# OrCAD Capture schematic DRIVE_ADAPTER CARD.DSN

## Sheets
1 03. Or'ing Circuit: size A4; title: XMC DRIVER ADAPTER CARD; rev: 3.00; note: 630-INT0222-01
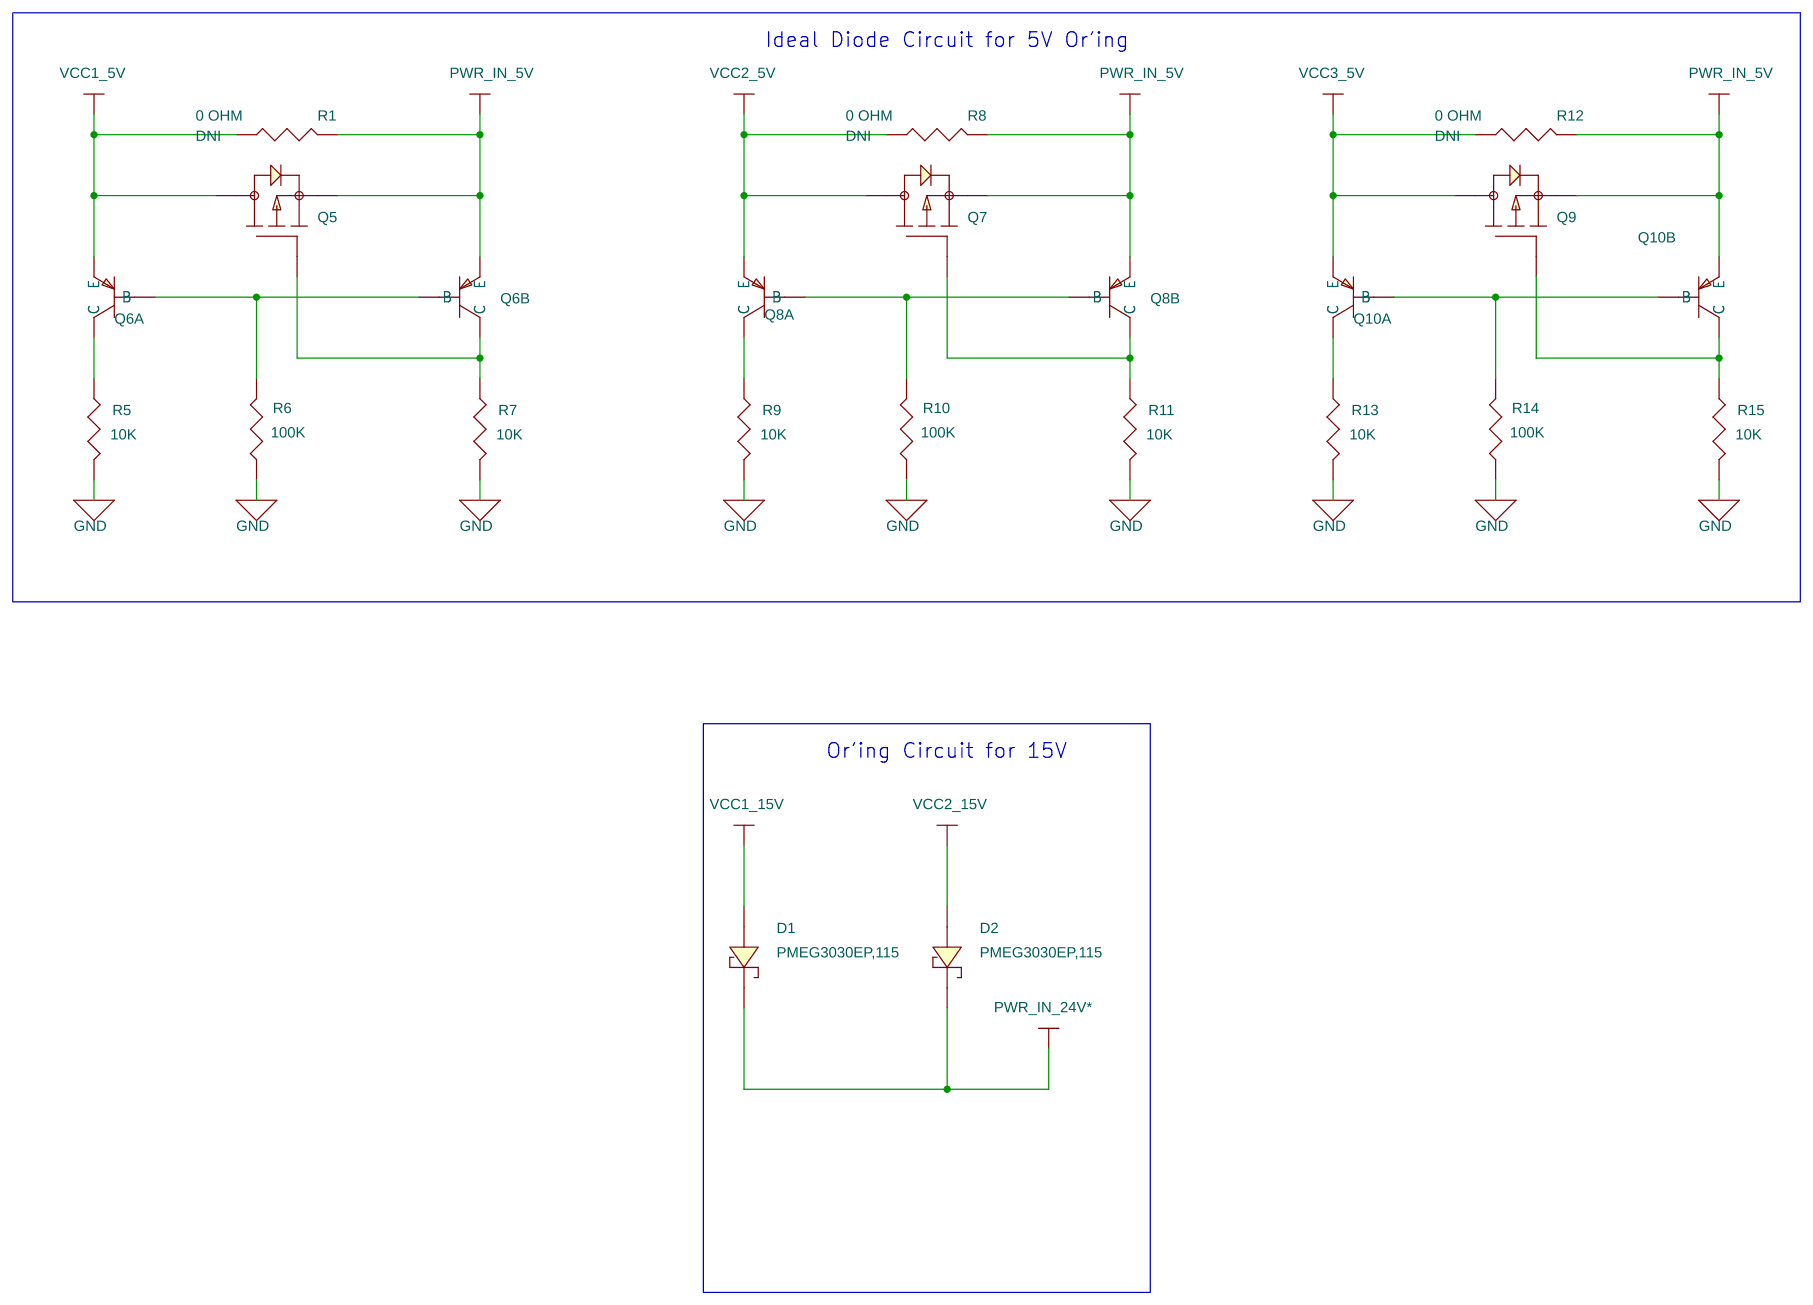
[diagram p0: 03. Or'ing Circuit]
2 01. Title Page
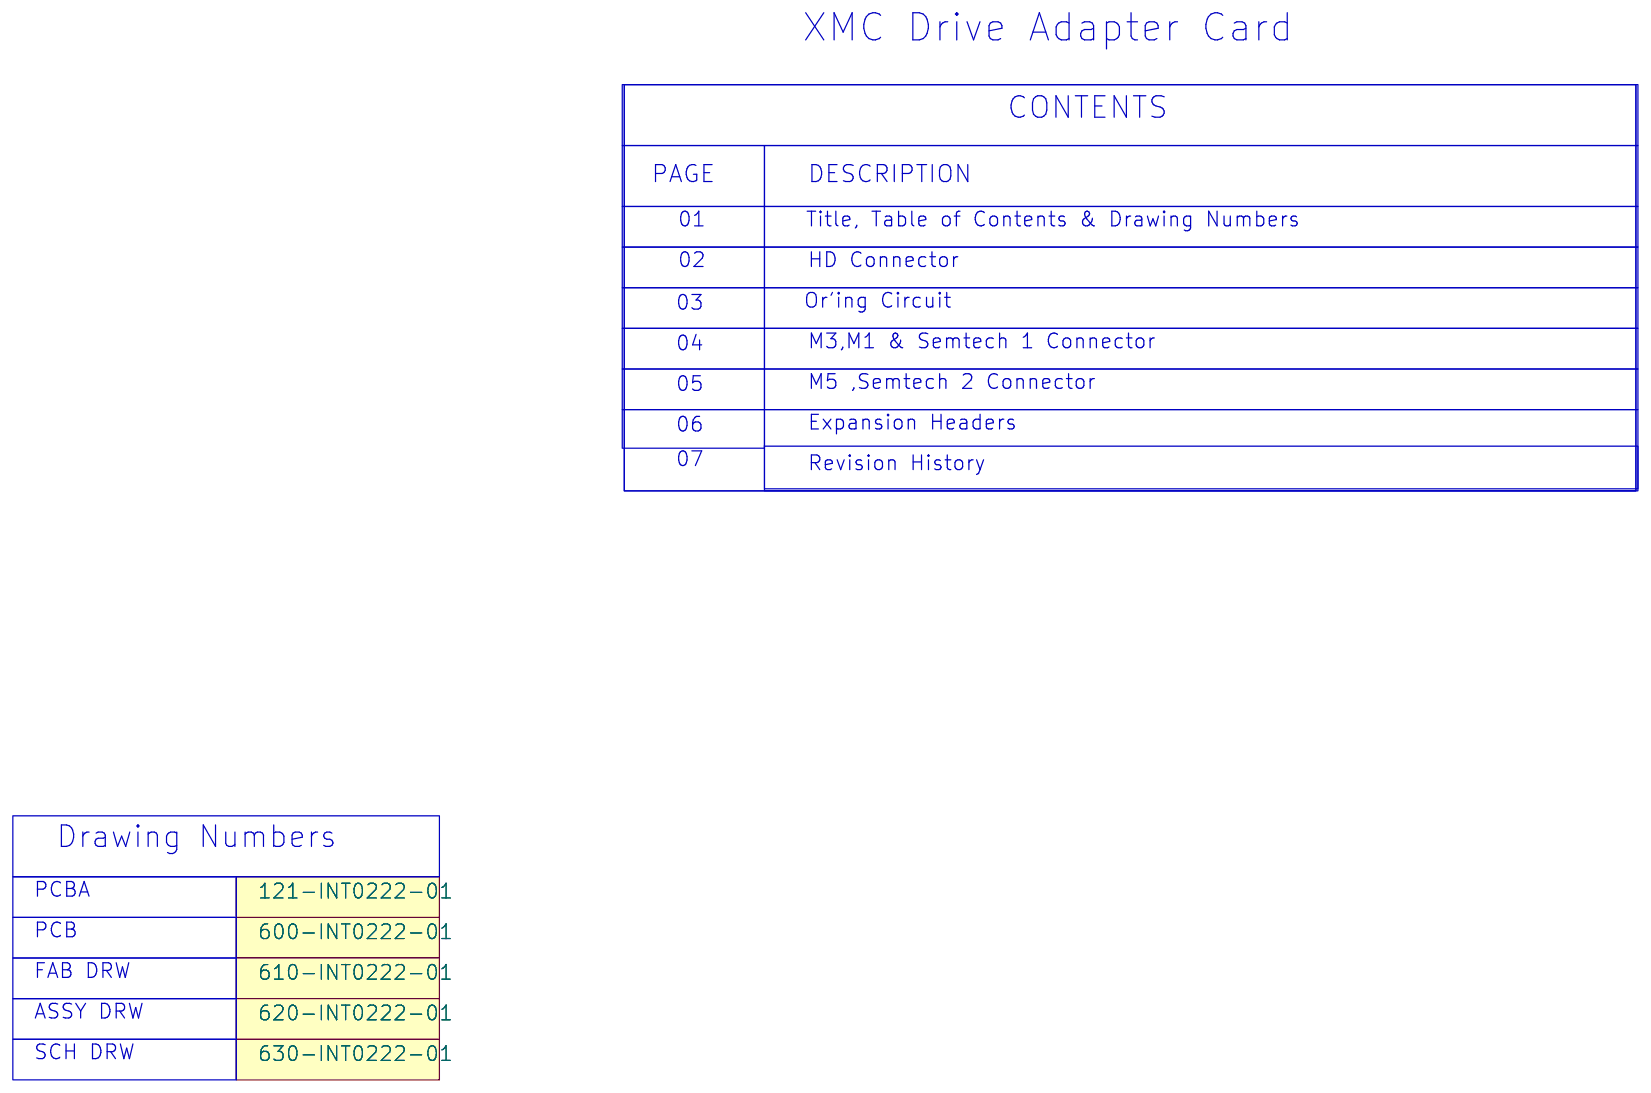
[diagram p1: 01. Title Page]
3 02. HD Connector: size A4
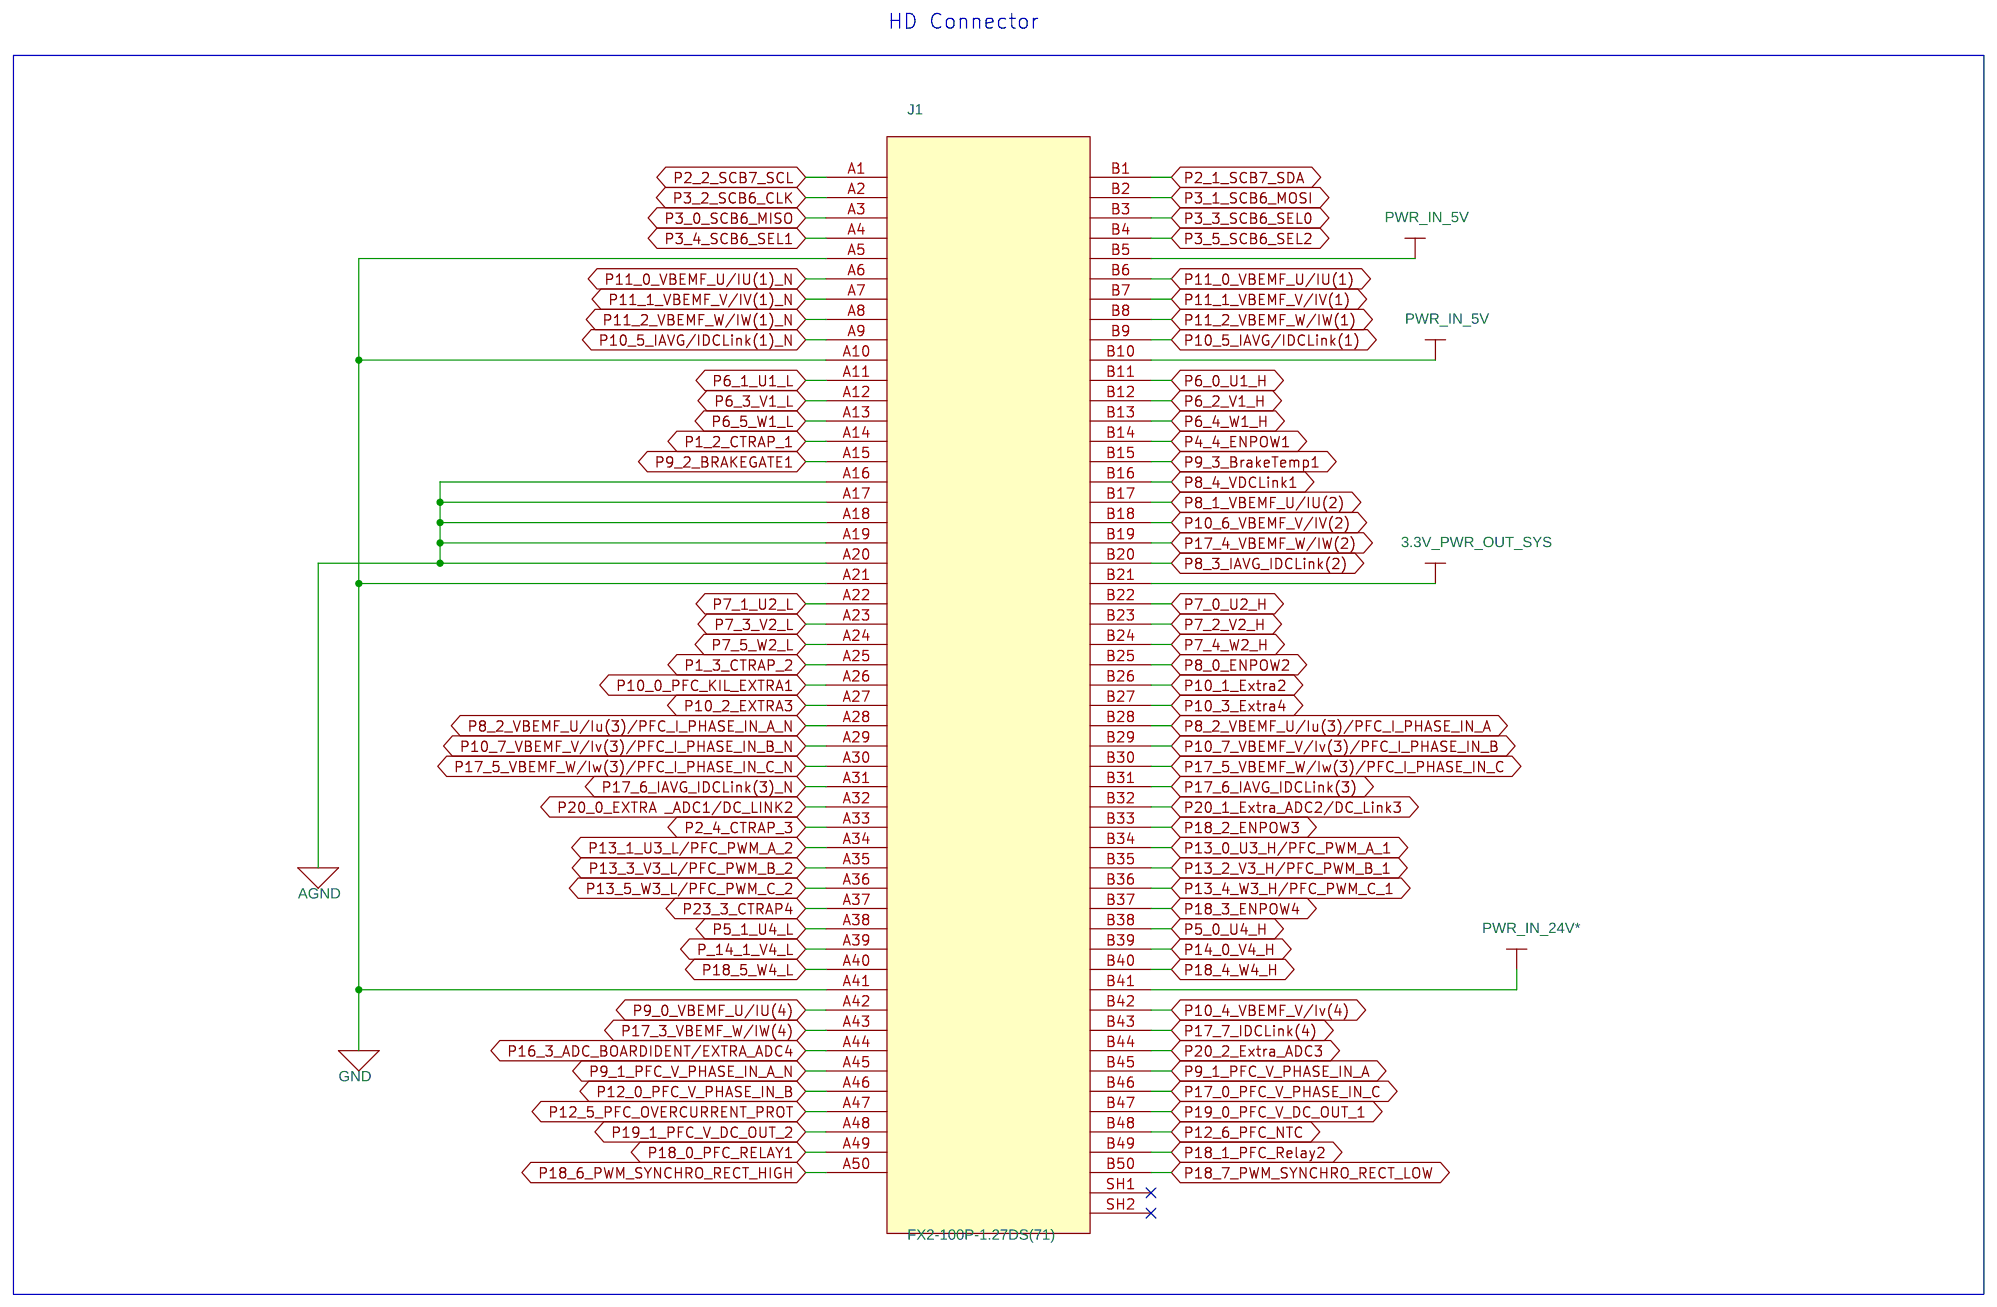
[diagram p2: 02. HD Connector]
4 04.M3,M1 & Semtech 1 Connector: size A4
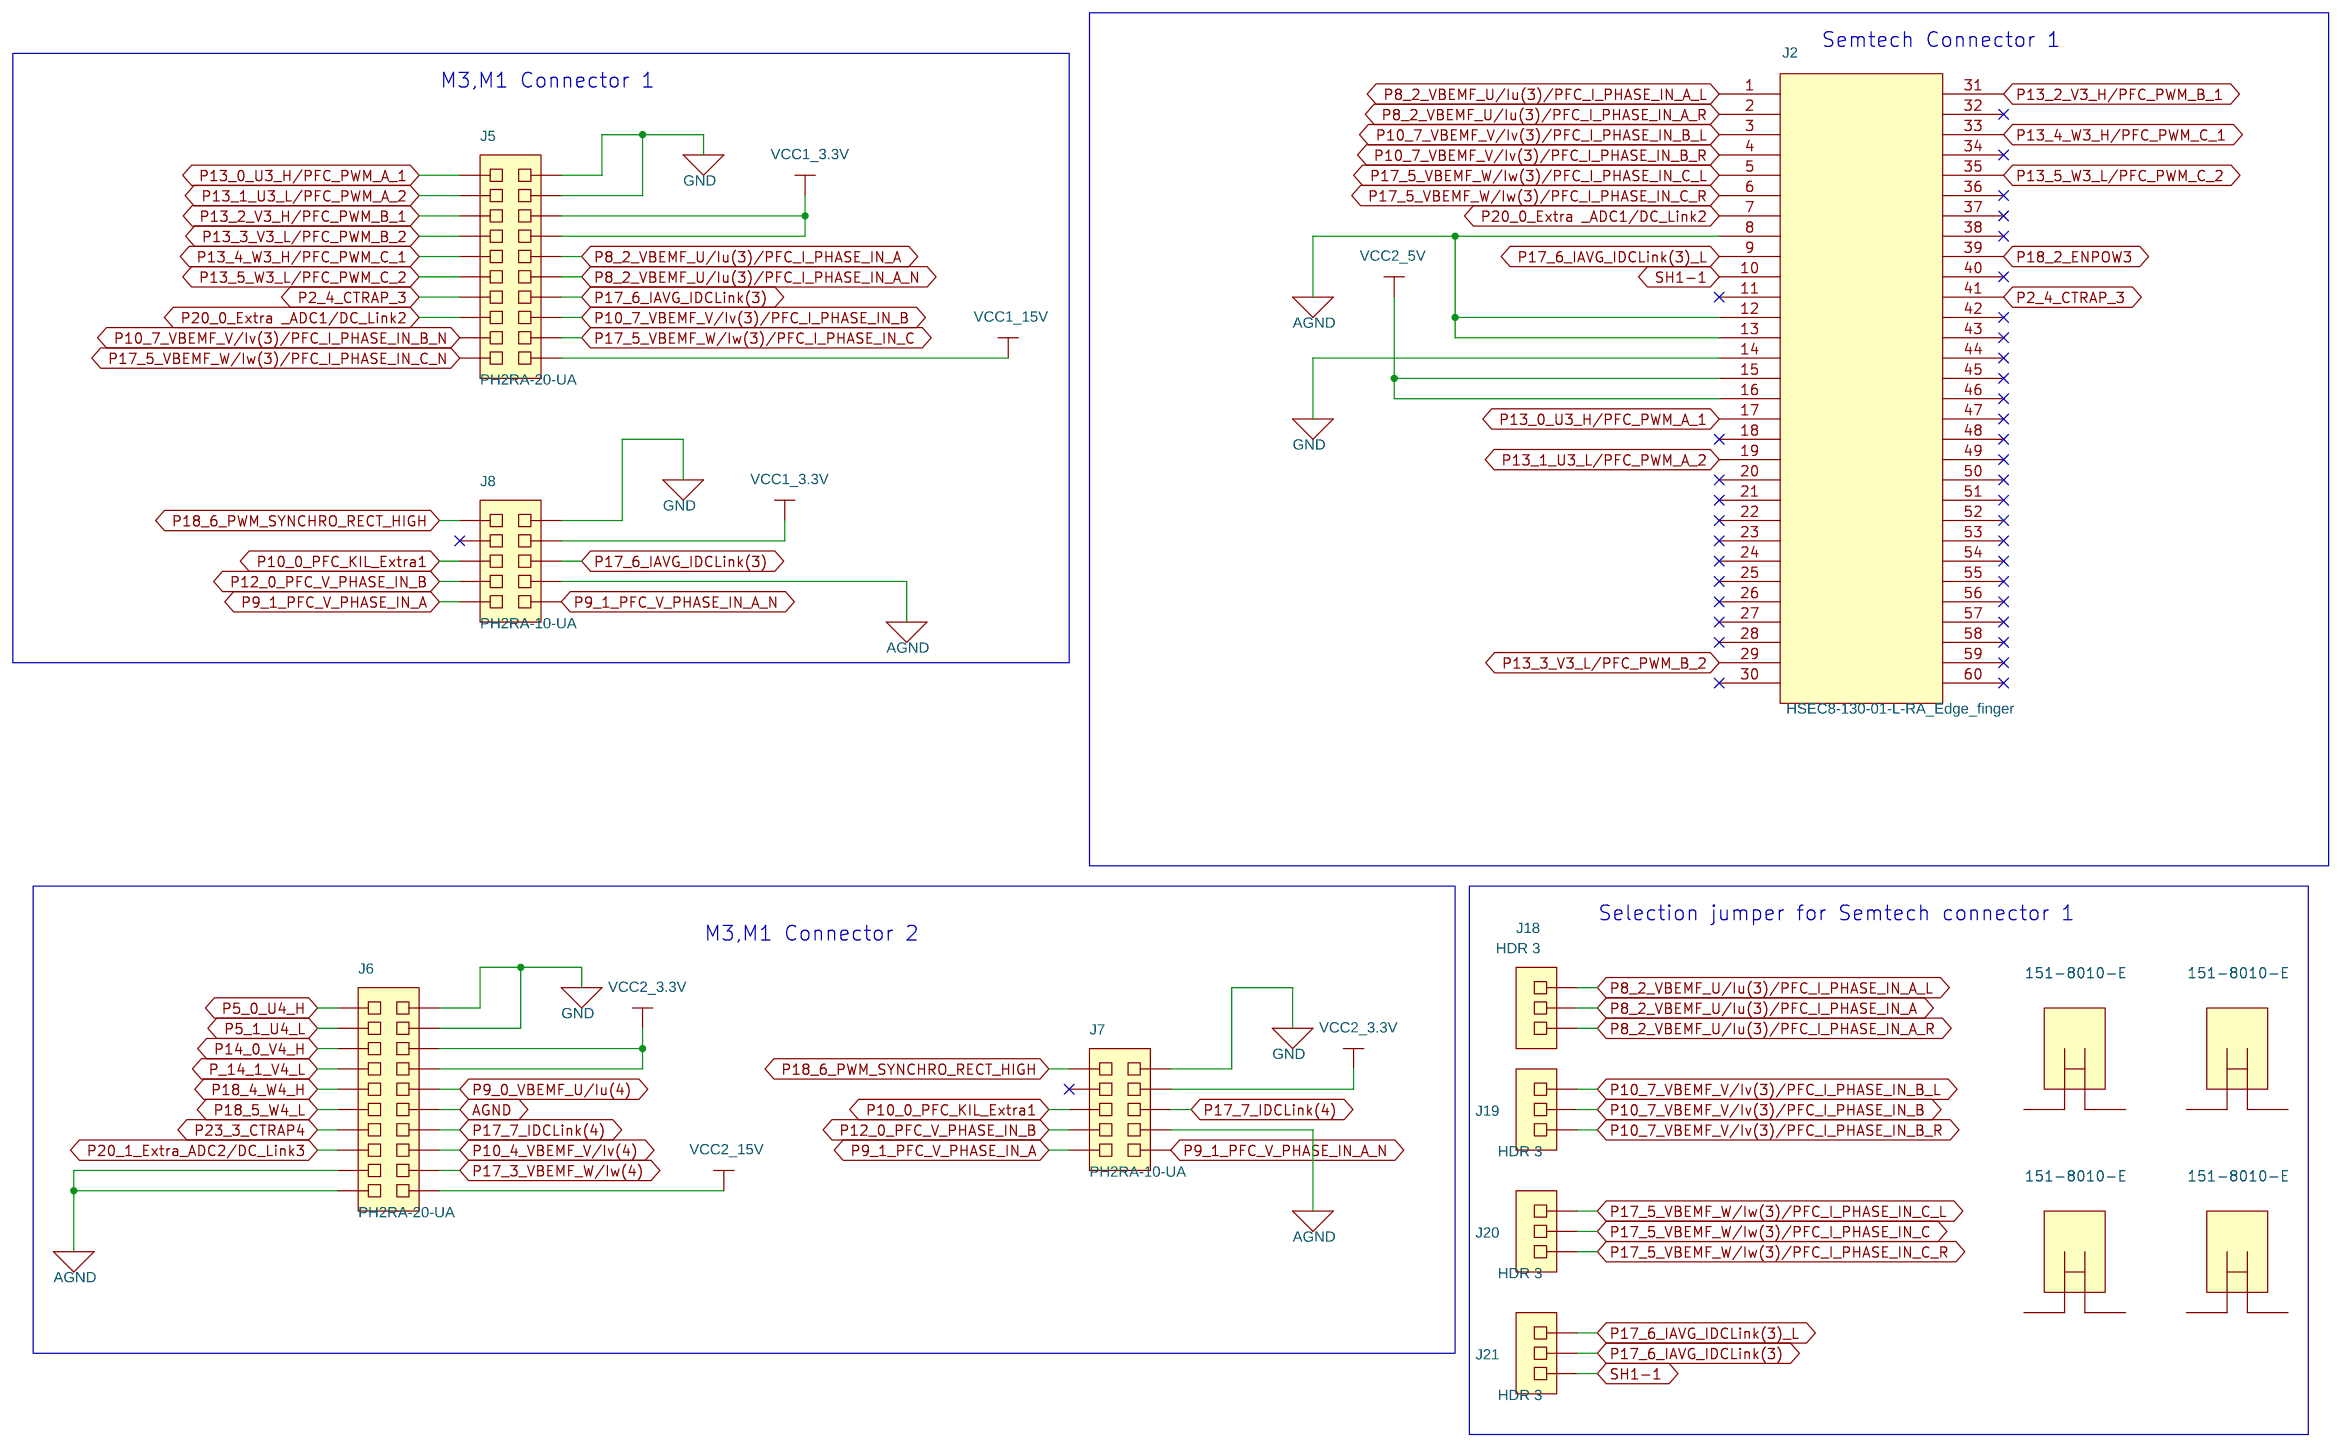
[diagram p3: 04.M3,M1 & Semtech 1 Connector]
5 05. M5 ,Semtech 2 Connector: size A4
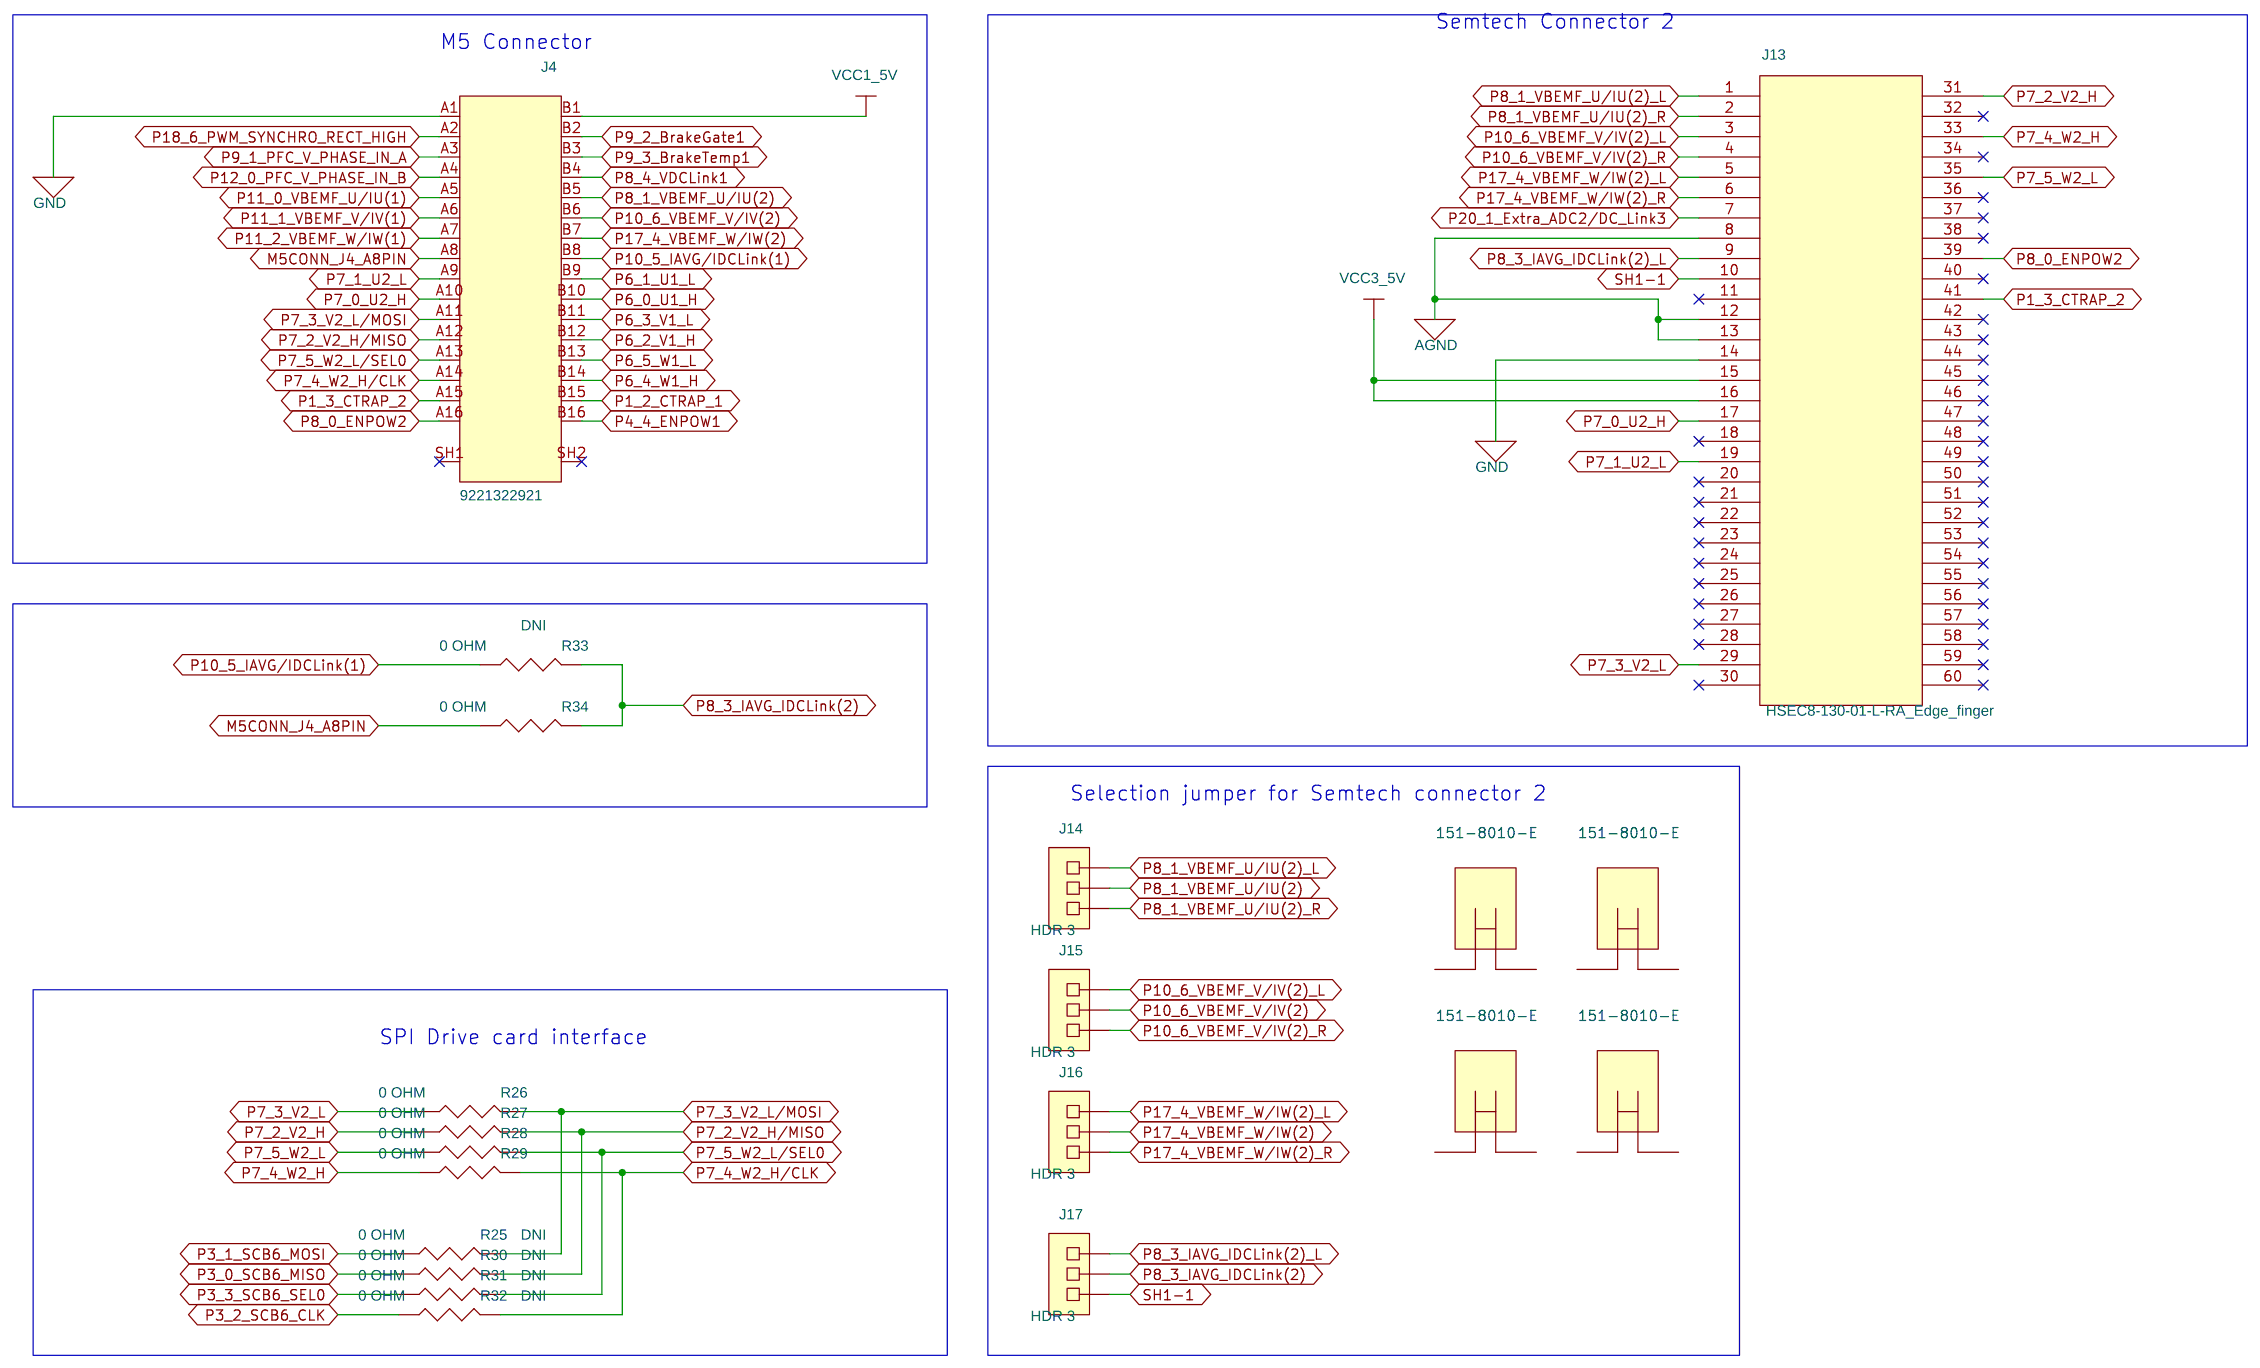
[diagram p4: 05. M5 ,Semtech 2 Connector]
6 06. Expansion Headers: size A4
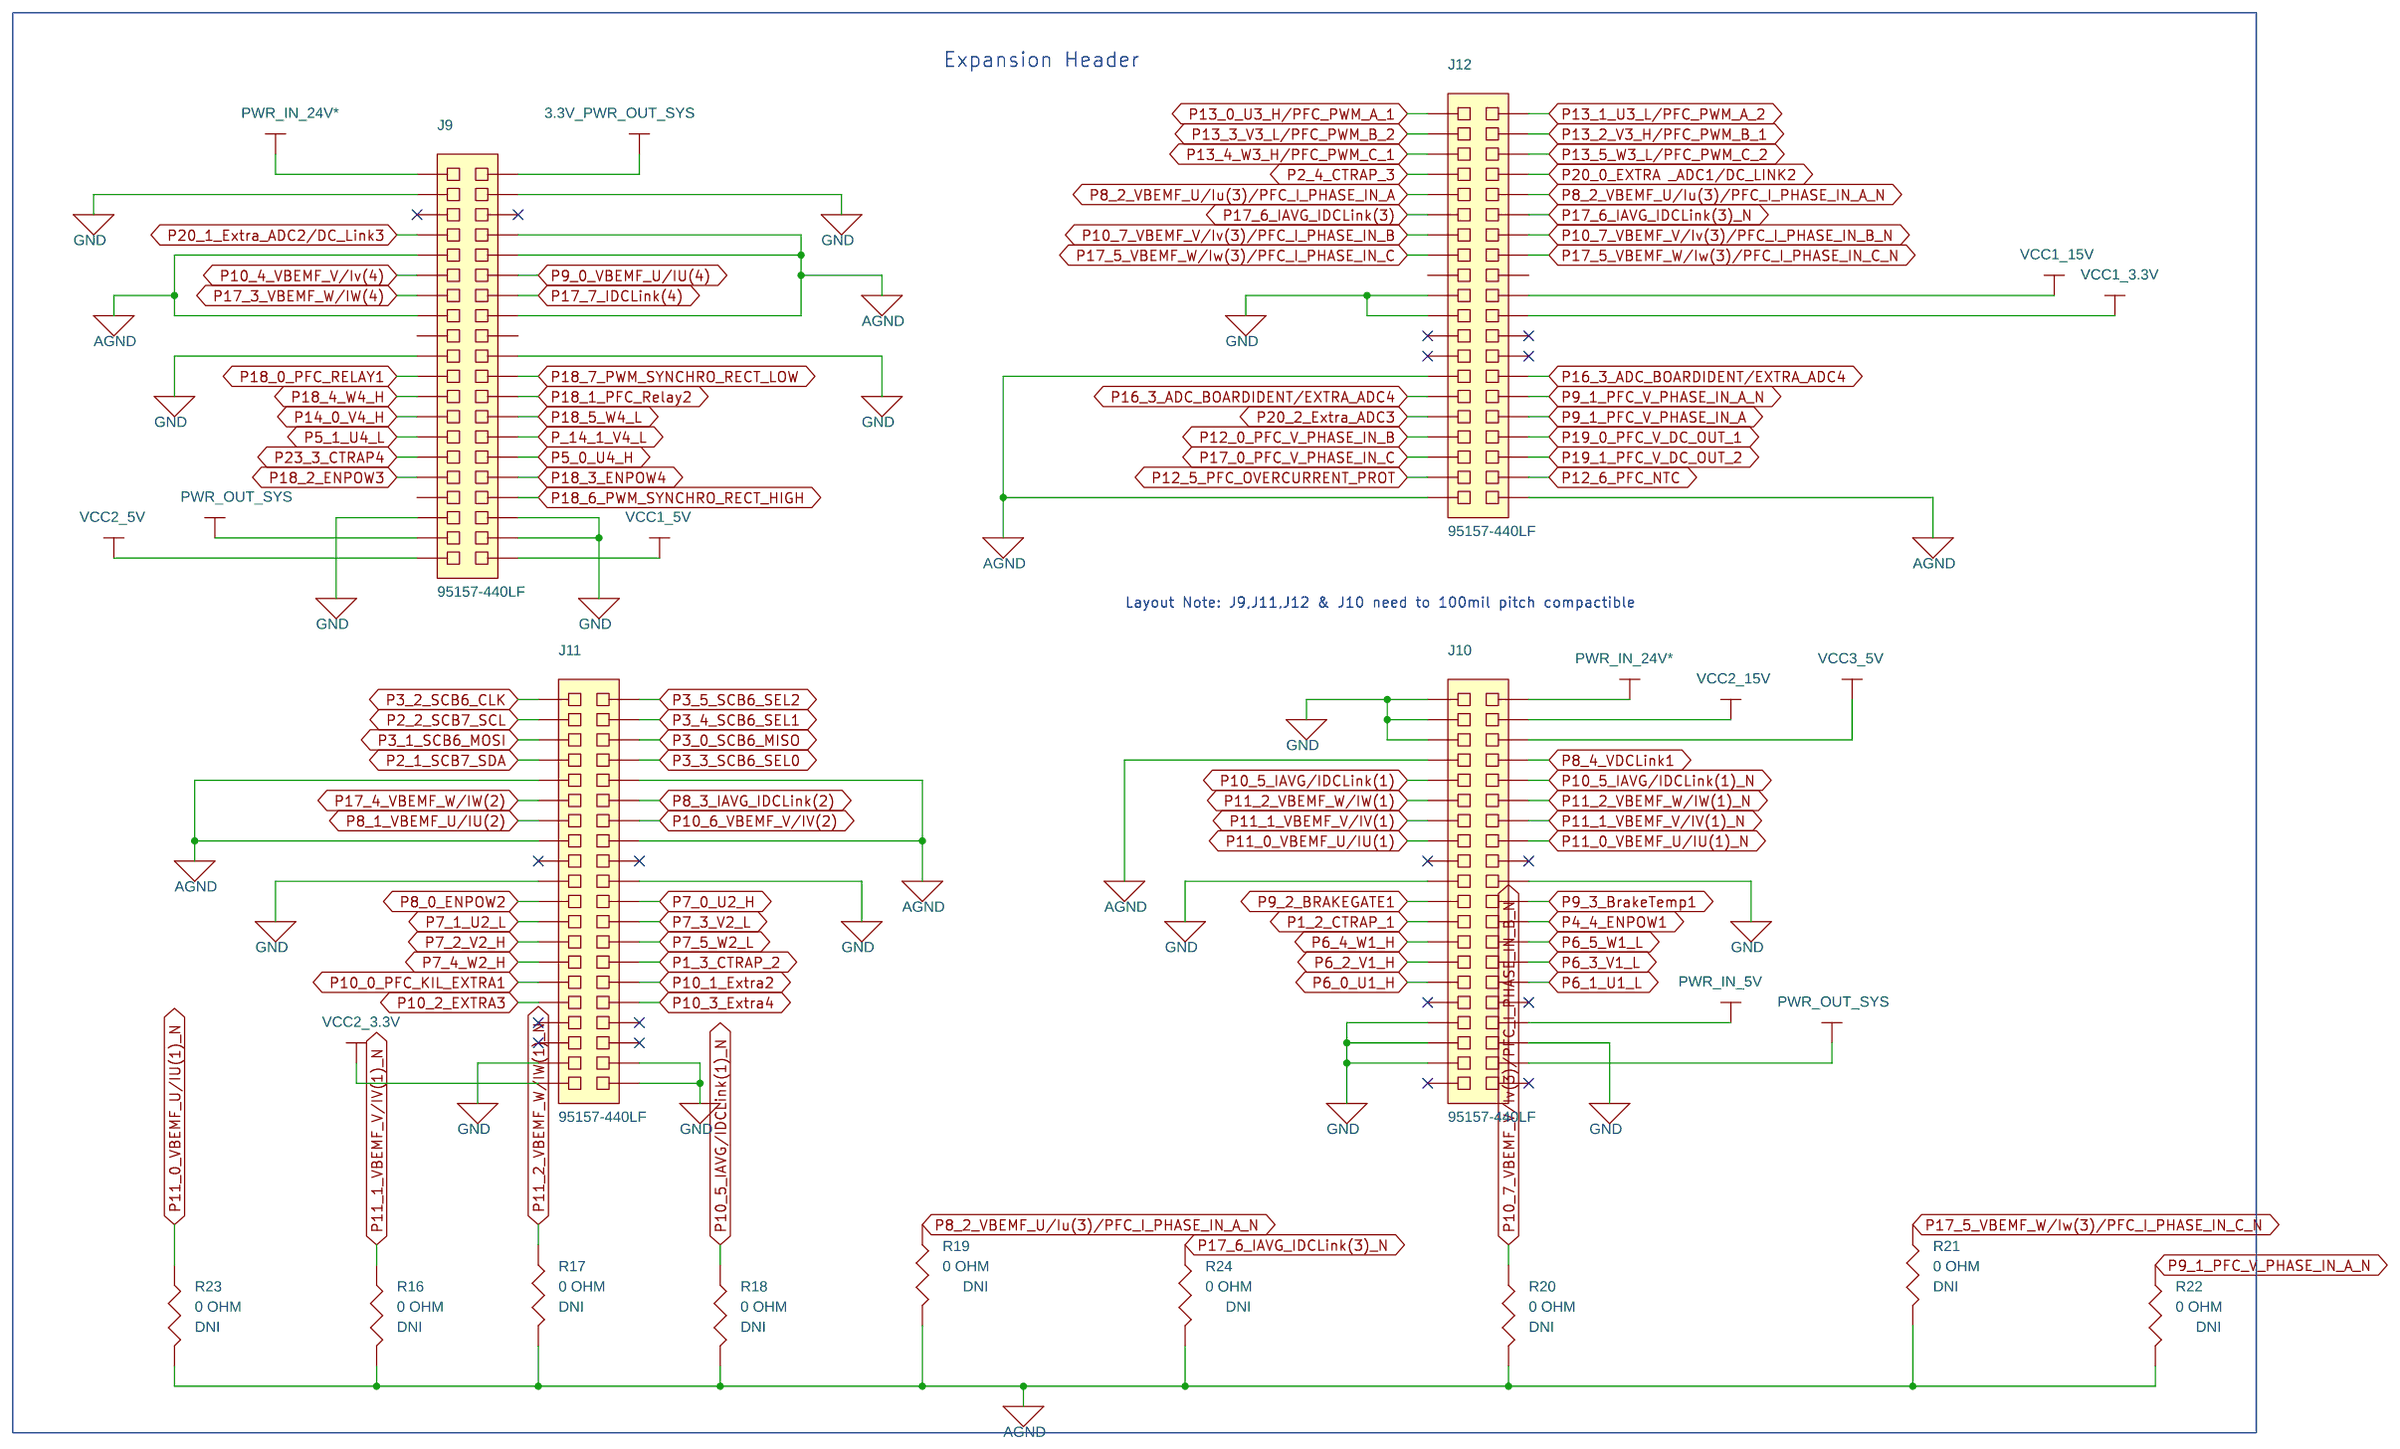
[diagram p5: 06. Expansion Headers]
7 07. Revision History
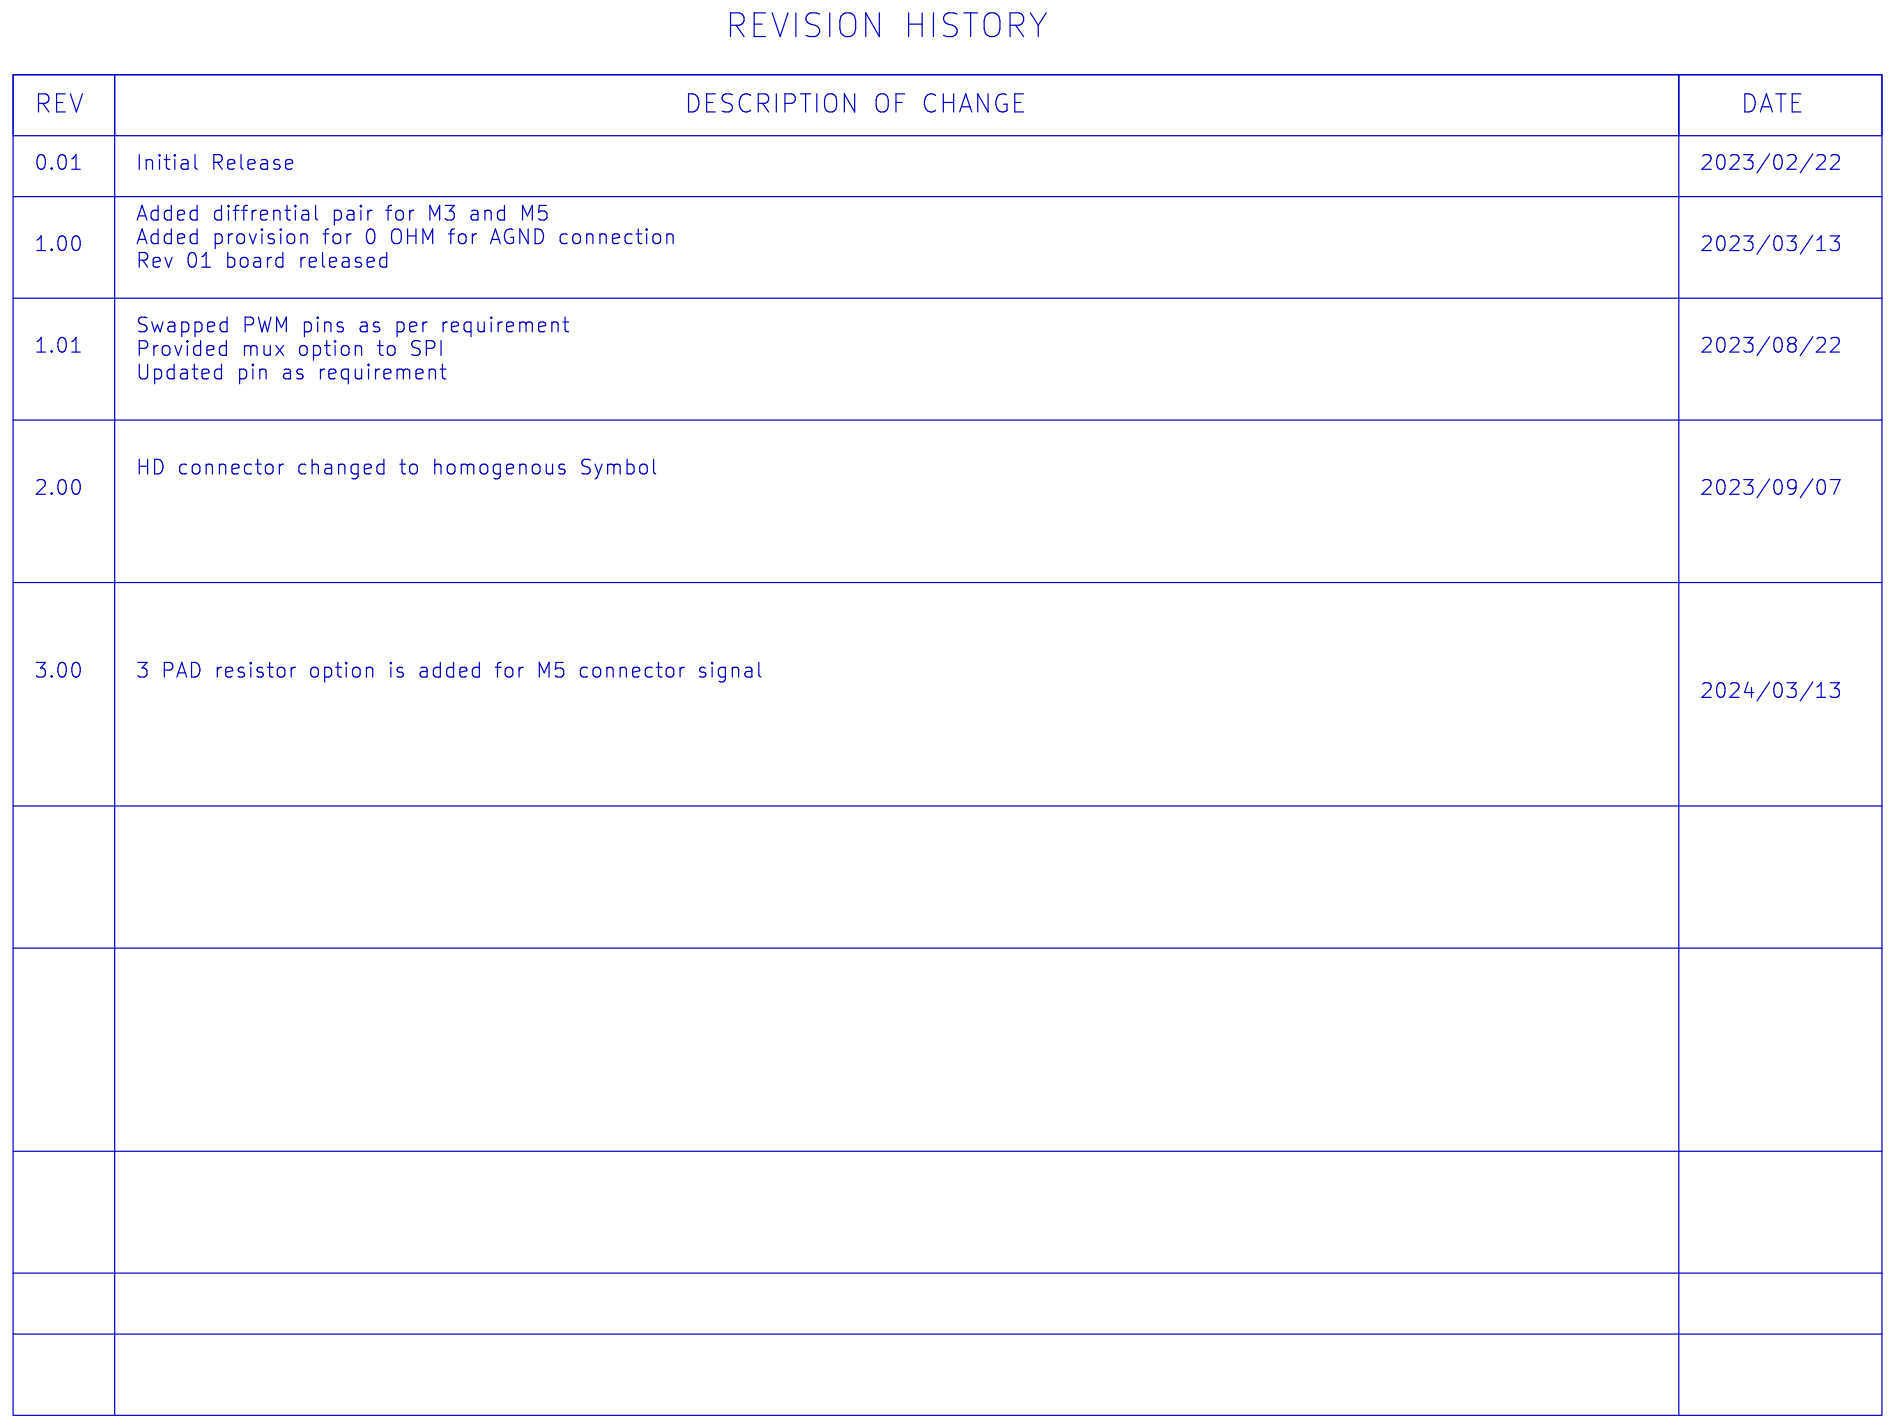
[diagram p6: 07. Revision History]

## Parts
sheet 01. Title Page
ACC1  121-INT0222-01  [TBD]
ACC2  600-INT0222-01  [TBD]
ACC3  610-INT0222-01  [TBD]
ACC4  620-INT0222-01  [TBD]
ACC5  630-INT0222-01  [TBD]
sheet 02. HD Connector
J1  FX2-100P-1.27DS(71)  [HIROSE_FX2-100P-1P27DS-71]
sheet 03. Or'ing Circuit
D1  PMEG3030EP,115  [DIO_NXP_SOD-128]
D2  PMEG3030EP,115  [DIO_NXP_SOD-128]
Q5  IRLML2244TRPbF  [SOT95P300X115-3N]
Q6  BCM857BS,115  [SOT65P210X110-6N]  (sections A,B)
Q7  IRLML2244TRPbF  [SOT95P300X115-3N]
Q8  BCM857BS,115  [SOT65P210X110-6N]  (sections A,B)
Q9  IRLML2244TRPbF  [SOT95P300X115-3N]
Q10  BCM857BS,115  [SOT65P210X110-6N]  (sections A,B)
R1  0 OHM  [RESC1608_0603N]
R5  10K  [RESC1005_0402N]
R6  100K  [RESC1005_0402N]
R7  10K  [RESC1005_0402N]
R8  0 OHM  [RESC1608_0603N]
R9  10K  [RESC1005_0402N]
R10  100K  [RESC1005_0402N]
R11  10K  [RESC1005_0402N]
R12  0 OHM  [RESC1608_0603N]
R13  10K  [RESC1005_0402N]
R14  100K  [RESC1005_0402N]
R15  10K  [RESC1005_0402N]
sheet 04.M3,M1 & Semtech 1 Connector
ACC10  151-8010-E  [TBD]
ACC11  151-8010-E  [TBD]
ACC12  151-8010-E  [TBD]
ACC13  151-8010-E  [TBD]
J2  HSEC8-130-01-L-RA_Edge_finger  [SAMTEC_HSEC8_130_EDGE]
J5  PH2RA-20-UA  [ADAMTECH_PH2RA-20-UA_CUST]
J6  PH2RA-20-UA  [ADAMTECH_PH2RA-20-UA_CUST]
J7  PH2RA-10-UA  [ADAMTECH_PH2RA-10-UA_CUST]
J8  PH2RA-10-UA  [ADAMTECH_PH2RA-10-UA_CUST]
J18  HDR 3  [CTST254P1X03_W260]
J19  HDR 3  [CTST254P1X03_W260]
J20  HDR 3  [CTST254P1X03_W260]
J21  HDR 3  [CTST254P1X03_W260]
sheet 05. M5 ,Semtech 2 Connector
ACC6  151-8010-E  [TBD]
ACC7  151-8010-E  [TBD]
ACC8  151-8010-E  [TBD]
ACC9  151-8010-E  [TBD]
J4  9221322921  [HARTING_9221322921]
J13  HSEC8-130-01-L-RA_Edge_finger  [SAMTEC_HSEC8_130_EDGE]
J14  HDR 3  [CTST254P1X03_W260]
J15  HDR 3  [CTST254P1X03_W260]
J16  HDR 3  [CTST254P1X03_W260]
J17  HDR 3  [CTST254P1X03_W260]
R25  0 OHM  [RESC1608_0603N]
R26  0 OHM  [RESC1608_0603N]
R27  0 OHM  [RESC1608_0603N]
R28  0 OHM  [RESC1608_0603N]
R29  0 OHM  [RESC1608_0603N]
R30  0 OHM  [RESC1608_0603N]
R31  0 OHM  [RESC1608_0603N]
R32  0 OHM  [RESC1608_0603N]
R33  0 OHM  [RESC1608_0603N]
R34  0 OHM  [RESC1608_0603N]
sheet 06. Expansion Headers
J9  95157-440LF  [AMPHENOL_95157-440LF]
J10  95157-440LF  [AMPHENOL_95157-440LF]
J11  95157-440LF  [AMPHENOL_95157-440LF]
J12  95157-440LF  [AMPHENOL_95157-440LF]
R16  0 OHM  [RESC1005_0402N]
R17  0 OHM  [RESC1005_0402N]
R18  0 OHM  [RESC1005_0402N]
R19  0 OHM  [RESC1005_0402N]
R20  0 OHM  [RESC1005_0402N]
R21  0 OHM  [RESC1005_0402N]
R22  0 OHM  [RESC1005_0402N]
R23  0 OHM  [RESC1005_0402N]
R24  0 OHM  [RESC1005_0402N]

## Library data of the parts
ACC1 = PCB: ASSY, PCBA, XMC Drive Adapter Board; DNI: DNI; Manufacturer: Cypress Approved CM; Manufacturer_PN: -NA-; Mfr_Name: Cypress Approved CM; Mfr_Part#: -NA-; Mfr_Part_Number: -NA-
ACC2 = PCB: PCB, BARE, XMC Drive Adapter Board; DNI: DNI; Manufacturer: Cypress Approved CM; Manufacturer_PN: -NA-; Mfr_Name: Cypress Approved CM; Mfr_Part#: -NA-; Mfr_Part_Number: -NA-
ACC3 = PCB: DRW, FABRICATION DRAWING, XMC Drive Adapter Board; DNI: DNI; Manufacturer: -NA-; Manufacturer_PN: -NA-; Mfr_Name: -NA-; Mfr_Part#: -NA-; Mfr_Part_Number: -NA-
ACC4 = PCB: DRW, ASSEMBLY DRAWING, XMC Drive Adapter Board; DNI: DNI; Manufacturer: -NA-; Manufacturer_PN: -NA-; Mfr_Name: -NA-; Mfr_Part#: -NA-; Mfr_Part_Number: -NA-
ACC5 = PCB: DRW, SCHEMATIC DRAWING, XMC Drive Adapter Board; DNI: DNI; Manufacturer: -NA-; Manufacturer_PN: -NA-; Mfr_Name: -NA-; Mfr_Part#: -NA-; Mfr_Part_Number: -NA-
J1 = FX2100P127DS71: CONN, BTB PLUG, 100POS R/A, SOLDER; CY_PN: 720-60608-01; Manufacturer: Hirose Electric Co Ltd
D1 D2 = DIO-SCHOTTKY: DIO, SCHOTTKY, 30V, 3A, SOD128, SURFACE MOUNT; Approved: Approved; CY_PN: 530-60216-01; Description1: Schottky Diodes & Rectifiers SCHOTTKY RECT 30V 3A; Device_File: 530-60216-01; Lifecycle: Active; Manufacturer: NXP; Operating_Temp: -55°C to 150°C; Package: SOD128; Part_Status: Unrel; Rating: 3A; Voltage: 30V
Q5 Q7 Q9 = IRLML2244TRPbF
Q6 Q8 Q10 = PNP-PNP-BCM857BS: TRANS 2PNP, 45V, 0.1A, 6TSSOP; Approved: Approved; CY_PN: 531-60042-01; Current: 100mA; Device_File: 531-60042-01; Lifecycle: Active; Manufacturer: Nexperia USA Inc.; Operating_Temp: 150°C(TJ); Package: SOT-363; Part_Status: Unrel; Power: 300mW; Voltage: 45V
R1 R8 R12 R25 R30-R33 = RES: RES, 0 OHM, JUMPER, 1A, 0603; CY_PN: 500-60037-01; DNI: DNI; Device_File: 500-60037-01; FPLIST: RESC1608_0603N,RESC1608_0603Q,RESC1608_0603M; Lifecycle: Active; Manufacturer: Yageo; Manufacturer_PN: RC0603JR-070RL; Operating_Temp: -55°C to 155°C; Package: 0603; Part_Status: In Prod; Rating: 1A; Tolerance: JUMPER; Wattage: 1/8W
R5 R7 R9 R11 R13 R15 = RES: RES, 10K, 5%, 1/16W, 0402; CY_PN: 500-60433-01; Device File: 500-60433-01; FPLIST: RESC1005_0402N,RESC1005_0402M; Manufacturer: Yageo; Manufacturer_PN: RC0402JR-0710KL; Operating_Temp: -55°C to 155°C; Rating: 1/16W; Tolerance: 5%
R6 R10 R14 = RES: RES, 100K, 5%, 1/16W, 0402; CY_PN: 500-60075-01; Device File: 500-60075-01; FPLIST: RESC1005_0402N,RESC1005_0402M; Manufacturer: Yageo; Manufacturer_PN: RC0402JR-07100KL; Rating: 1/16W; Tolerance: 5%
ACC6-ACC13 = Jumper_Shunt: HW, JUMPER, CLOSE TYPE, 6mm, 2.54mm Pitch, BLACK; CY_PN: 700-60076-01; Description1: 1A Max, 0.015OHM, Nickel; Manufacturer: Kobiconn; Operating_Temp: -55°C to 105°C; Part_Status: In Prod
J2 J13 = EDGE_CARD_HSEC8: Edge finger connector, 60POS, RA; Approved: Approved; CY_PN: NA; DNI: DNI; Description1: Edge finger connector for HSEC8-130-01-L-RA; FPLIST: SAMTEC_HSEC8_130_EDGE,SAMTEC_HSEC8_130_EDGE_MATING; Lifecycle: NA; Manufacturer: NA; Manufacturer_PN: NA; Part_Status: NA
J5 J6 = PLG-20-ODD-EVEN-J: CONN, HEADER, R/A, 20POS, 2.54MM; Approved: Approved; CY_PN: 710-60129-01; Conatct_Length: 5.97mm; Contact_Finish: GOLD; Current_Rating: 3A; Device_File: 710-60129-01; FPLIST: ADAMTECH_PH2RA-20-UA,ADAMTECH_PH2RA-20-UA_CUST; Lifecycle: Active; Manufacturer: Adam Tech; Mated_Height: NA; Operating_Temp: -55°C ~ 125°C; Part_Status: Unrel; Pin_Pitch: 2.54mm; Pins: 20; Row_pitch: NA; Rows: 2; Shrouding: Unshrouded
J7 J8 = PLG-10-ODD-EVEN-J: CONN,  HEADER, R/A, 10POS, 2.54MM; Approved: Approved; CY_PN: 710-60130-01; Conatct_Length: 5.97mm; Contact_Finish: GOLD; Current_Rating: 3A; Device_File: 710-60130-01; FPLIST: ADAMTECH_PH2RA-10-UA,ADAMTECH_PH2RA-10-UA_CUST; Lifecycle: Active; Manufacturer: Adam Tech; Mated_Height: NA; Operating_Temp: -55°C ~ 125°C; Part_Status: Unrel; Pin_Pitch: 2.54mm; Pins: 10; Row_pitch: NA; Rows: 2; Shrouding: Unshrouded
J14-J21 = PLG-3-J: CONN, HDR, MALE, SINGLE, 3POS, 2.54mm, TIN, STR, TH; CY_PN: 720-60018-01; Conatct_Length: 5.84mm; Contact_Finish: TIN; Current_Rating: 3A; Device_File: 720-60018-01; Lifecycle: Active; Manufacturer: Sullins; Manufacturer_PN: PREC003SAAN-RC; Mated_Height: 8.34mm; Operating_Temp: -40°C to 105°C; Part_Status: In Prod; Pin_Pitch: 2.54; Pins: 3; Row_pitch: NA; Rows: 1; Shrouding: Unshrouded
J4 = PLG_2x16_SHRD: CONN, DIN HDR, 32POS, PCB, RA; Approved: Approved; CY_PN: 720-60612-01; Conatct_Length: NA; Contact_Finish: NA; Current_Rating: 2A; Device_File: 720-60612-01; Lifecycle: Active; Manufacturer: HARTING; Mated_Height: NA; Operating_Temp: -55°C ~ 125°C; Part_Status: Unrel; Pin_Pitch: 2.54mm; Pins: 32; Row_pitch: NA; Rows: 2; Shrouding: NA
R26-R29 R34 = RES: RES, 0 OHM, JUMPER, 1A, 0603; CY_PN: 500-60037-01; Device_File: 500-60037-01; FPLIST: RESC1608_0603N,RESC1608_0603Q,RESC1608_0603M; Lifecycle: Active; Manufacturer: Yageo; Manufacturer_PN: RC0603JR-070RL; Operating_Temp: -55°C to 155°C; Package: 0603; Part_Status: In Prod; Rating: 1A; Tolerance: JUMPER; Wattage: 1/8W
J9-J12 = 95157-440LF_PLG-40-C-B: CONN, HEADER, SMD 40POS, 2.54MM; Approved: Approved; CY_PN: 710-60133-01; Conatct_Length: NA; Contact_Finish: Tin; Current_Rating: 3A; Device_File: 710-60133-01; Lifecycle: Active; Manufacturer: Amphenol; Mated_Height: NA; Operating_Temp: -65°C ~ 130°C; Part_Status: Unrel; Pin_Pitch: 2.54mm; Pins: 40; Row_pitch: NA; Rows: 2; Shrouding: Unshrouded
R16-R24 = RES: RES, Fixed, 0 OHM, JUMPER, 0.63A, 0402; CY_PN: 500-60007-01; DNI: DNI; Device_File: 500-60007-01; FPLIST: RESC1005_0402N,RESC1005_0402M; Lifecycle: Active; Manufacturer: Panasonic; Manufacturer_PN: ERJ-2GE0R00X; Operating_Temp: -55°C to 155°C; Package: 0402; Part_Status: In Production; Rating: 0.63A; Tolerance: JUMPER

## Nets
3.3V_PWR_OUT_SYS: J1.B21 J9.B1
AGND: J1.A16 J1.A17 J1.A18 J1.A19 J1.A20 J2.8 J2.12 J2.13 J6.12 J6.17 J6.19 J7.8 J8.8 J9.B4 J9.B5 J9.B8 J9.C5 J9.C8 J10.C4 J11.B5 J11.B8 J11.C5 J11.C8 J12.B20 J12.C14 J12.C20 J13.8 J13.12 J13.13 R16.2 R17.2 R18.2 R19.2 R20.2 R21.2 R22.2 R23.2 R24.2
GND: J1.A5 J1.A10 J1.A21 J1.A41 J2.14 J4.A1 J5.2 J5.4 J6.2 J6.4 J7.2 J8.2 J9.B2 J9.B10 J9.B18 J9.B19 J9.C2 J9.C10 J9.C18 J10.B10 J10.B18 J10.C1 J10.C2 J10.C3 J10.C10 J10.C17 J10.C18 J10.C19 J11.B10 J11.B19 J11.B20 J11.C10 J11.C19 J12.C10 J12.C11 J13.14 R5.2 R6.1 R7.2 R9.2 R10.1 R11.2 R13.2 R14.1 R15.2
VCC1_3.3V: J5.6 J5.8 J8.4 J12.B11
VCC1_5V: J4.B1 J9.B20 Q5.D Q6.1(E) R1.1
VCC1_15V: D1.A J5.20 J12.B10
VCC2_3.3V: J6.6 J6.8 J7.4 J11.C20
VCC2_5V: J2.15 J2.16 J9.C20 Q7.D Q8.1(E) R8.1
VCC2_15V: D2.A J6.20 J10.B2
VCC3_5V: J10.B3 J13.15 J13.16 Q9.D Q10.1(E) R12.1
M5CONN_J4_A8PIN: J4.A8 R34.1
P1_2_CTRAP_1: J1.A14 J4.B15 J10.C12
P1_3_CTRAP_2: J1.A25 J4.A15 J11.B14 J13.41
P2_1_SCB7_SDA: J1.B1 J11.C4
P2_2_SCB7_SCL: J1.A1 J11.C2
P2_4_CTRAP_3: J1.A33 J2.41 J5.13 J12.C4
P3_0_SCB6_MISO: J1.A3 J11.B3 R30.1
P3_1_SCB6_MOSI: J1.B2 J11.C3 R25.1
P3_2_SCB6_CLK: J1.A2 J11.C1 R32.1
P3_3_SCB6_SEL0: J1.B3 J11.B4 R31.1
P3_4_SCB6_SEL1: J1.A4 J11.B2
P3_5_SCB6_SEL2: J1.B4 J11.B1
P4_4_ENPOW1: J1.B14 J4.B16 J10.B12
P5_0_U4_H: J1.B38 J6.1 J9.B15
P5_1_U4_L: J1.A38 J6.3 J9.C14
P6_0_U1_H: J1.B11 J4.B10 J10.C15
P6_1_U1_L: J1.A11 J4.B9 J10.B15
P6_2_V1_H: J1.B12 J4.B12 J10.C14
P6_3_V1_L: J1.A12 J4.B11 J10.B14
P6_4_W1_H: J1.B13 J4.B14 J10.C13
P6_5_W1_L: J1.A13 J4.B13 J10.B13
P7_0_U2_H: J1.B22 J4.A10 J11.B11 J13.17
P7_1_U2_L: J1.A22 J4.A9 J11.C12 J13.19
P7_2_V2_H: J1.B23 J11.C13 J13.31 R27.1
P7_2_V2_H/MISO: J4.A12 R27.2 R30.2
P7_3_V2_L: J1.A23 J11.B12 J13.29 R26.1
P7_3_V2_L/MOSI: J4.A11 R25.2 R26.2
P7_4_W2_H: J1.B24 J11.C14 J13.33 R29.1
P7_4_W2_H/CLK: J4.A14 R29.2 R32.2
P7_5_W2_L: J1.A24 J11.B13 J13.35 R28.1
P7_5_W2_L/SEL0: J4.A13 R28.2 R31.2
P8_0_ENPOW2: J1.B25 J4.A16 J11.C11 J13.39
P8_1_VBEMF_U/IU(2): J1.B17 J4.B5 J11.C7 J14.2
P8_1_VBEMF_U/IU(2)_L: J13.1 J14.1
P8_1_VBEMF_U/IU(2)_R: J13.2 J14.3
P8_2_VBEMF_U/Iu(3)/PFC_I_PHASE_IN_A: J1.B28 J5.10 J12.C5 J18.2
P8_2_VBEMF_U/Iu(3)/PFC_I_PHASE_IN_A_L: J2.1 J18.1
P8_2_VBEMF_U/Iu(3)/PFC_I_PHASE_IN_A_N: J1.A28 J5.12 J12.B5 R19.1
P8_2_VBEMF_U/Iu(3)/PFC_I_PHASE_IN_A_R: J2.2 J18.3
P8_3_IAVG_IDCLink(2): J1.B20 J11.B6 J17.2 R33.2 R34.2
P8_3_IAVG_IDCLink(2)_L: J13.9 J17.1
P8_4_VDCLink1: J1.B16 J4.B4 J10.B4
P9_0_VBEMF_U/IU(4): J1.A42 J6.10 J9.B6
P9_1_PFC_V_PHASE_IN_A: J1.B45 J4.A3 J7.9 J8.9 J12.B16
P9_1_PFC_V_PHASE_IN_A_N: J1.A45 J7.10 J8.10 J12.B15 R22.1
P9_2_BRAKEGATE1: J1.A15 J4.B2 J10.C11
P9_3_BrakeTemp1: J1.B15 J4.B3 J10.B11
P10_0_PFC_KIL_EXTRA1: J1.A26 J7.5 J8.5 J11.C15
P10_1_Extra2: J1.B26 J11.B15
P10_2_EXTRA3: J1.A27 J11.C16
P10_3_Extra4: J1.B27 J11.B16
P10_4_VBEMF_V/Iv(4): J1.B42 J6.16 J9.C6
P10_5_IAVG/IDCLink(1): J1.B9 J4.B8 J10.C5 R33.1
P10_5_IAVG/IDCLink(1)_N: J1.A9 J10.B5 R18.1
P10_6_VBEMF_V/IV(2): J1.B18 J4.B6 J11.B7 J15.2
P10_6_VBEMF_V/IV(2)_L: J13.3 J15.1
P10_6_VBEMF_V/IV(2)_R: J13.4 J15.3
P10_7_VBEMF_V/Iv(3)/PFC_I_PHASE_IN_B: J1.B29 J5.16 J12.C7 J19.2
P10_7_VBEMF_V/Iv(3)/PFC_I_PHASE_IN_B_L: J2.3 J19.1
P10_7_VBEMF_V/Iv(3)/PFC_I_PHASE_IN_B_N: J1.A29 J5.17 J12.B7 R20.1
P10_7_VBEMF_V/Iv(3)/PFC_I_PHASE_IN_B_R: J2.4 J19.3
P11_0_VBEMF_U/IU(1): J1.B6 J4.A5 J10.C8
P11_0_VBEMF_U/IU(1)_N: J1.A6 J10.B8 R23.1
P11_1_VBEMF_V/IV(1): J1.B7 J4.A6 J10.C7
P11_1_VBEMF_V/IV(1)_N: J1.A7 J10.B7 R16.1
P11_2_VBEMF_W/IW(1): J1.B8 J4.A7 J10.C6
P11_2_VBEMF_W/IW(1)_N: J1.A8 J10.B6 R17.1
P12_0_PFC_V_PHASE_IN_B: J1.A46 J4.A4 J7.7 J8.7 J12.C17
P12_5_PFC_OVERCURRENT_PROT: J1.A47 J12.C19
P12_6_PFC_NTC: J1.B48 J12.B19
P13_0_U3_H/PFC_PWM_A_1: J1.B34 J2.17 J5.1 J12.C1
P13_1_U3_L/PFC_PWM_A_2: J1.A34 J2.19 J5.3 J12.B1
P13_2_V3_H/PFC_PWM_B_1: J1.B35 J2.31 J5.5 J12.B2
P13_3_V3_L/PFC_PWM_B_2: J1.A35 J2.29 J5.7 J12.C2
P13_4_W3_H/PFC_PWM_C_1: J1.B36 J2.33 J5.9 J12.C3
P13_5_W3_L/PFC_PWM_C_2: J1.A36 J2.35 J5.11 J12.B3
P14_0_V4_H: J1.B39 J6.5 J9.C13
P16_3_ADC_BOARDIDENT/EXTRA_ADC4: J1.A44 J12.B14 J12.C15
P17_0_PFC_V_PHASE_IN_C: J1.B46 J12.C18
P17_3_VBEMF_W/IW(4): J1.A43 J6.18 J9.C7
P17_4_VBEMF_W/IW(2): J1.B19 J4.B7 J11.C6 J16.2
P17_4_VBEMF_W/IW(2)_L: J13.5 J16.1
P17_4_VBEMF_W/IW(2)_R: J13.6 J16.3
P17_5_VBEMF_W/Iw(3)/PFC_I_PHASE_IN_C: J1.B30 J5.18 J12.C8 J20.2
P17_5_VBEMF_W/Iw(3)/PFC_I_PHASE_IN_C_L: J2.5 J20.1
P17_5_VBEMF_W/Iw(3)/PFC_I_PHASE_IN_C_N: J1.A30 J5.19 J12.B8 R21.1
P17_5_VBEMF_W/Iw(3)/PFC_I_PHASE_IN_C_R: J2.6 J20.3
P17_6_IAVG_IDCLink(3): J1.B31 J5.14 J8.6 J12.C6 J21.2
P17_6_IAVG_IDCLink(3)_L: J2.9 J21.1
P17_6_IAVG_IDCLink(3)_N: J1.A31 J12.B6 R24.1
P17_7_IDCLink(4): J1.B43 J6.14 J7.6 J9.B7
P18_0_PFC_RELAY1: J1.A49 J9.C11
P18_1_PFC_Relay2: J1.B49 J9.B12
P18_2_ENPOW3: J1.B33 J2.39 J9.C16
P18_3_ENPOW4: J1.B37 J9.B16
P18_4_W4_H: J1.B40 J6.9 J9.C12
P18_5_W4_L: J1.A40 J6.11 J9.B13
P18_6_PWM_SYNCHRO_RECT_HIGH: J1.A50 J4.A2 J7.1 J8.1 J9.B17
P18_7_PWM_SYNCHRO_RECT_LOW: J1.B50 J9.B11
P19_0_PFC_V_DC_OUT_1: J1.B47 J12.B17
P19_1_PFC_V_DC_OUT_2: J1.A48 J12.B18
P20_0_EXTRA _ADC1/DC_LINK2: J1.A32 J2.7 J5.15 J12.B4
P20_1_Extra_ADC2/DC_Link3: J1.B32 J6.15 J9.C4 J13.7
P20_2_Extra_ADC3: J1.B44 J12.C16
P23_3_CTRAP4: J1.A37 J6.13 J9.C15
P_14_1_V4_L: J1.A39 J6.7 J9.B14
PWR_IN_5V: J1.B5 J1.B10 J10.B17 Q5.S Q6.4(E) Q7.S Q8.4(E) Q9.S Q10.4(E) R1.2 R8.2 R12.2
PWR_IN_24V*: D1.K D2.K J1.B41 J9.C1 J10.B1
PWR_OUT_SYS: J9.C19 J10.B19
SH1-1: J2.10 J13.10 J17.3 J21.3
N2988165: Q5.G Q6.3(C) R7.1
N2988205: Q7.G Q8.3(C) R11.1
N2988245: Q9.G Q10.3(C) R15.1
N2988267: Q6.2(B) Q6.5(B) R6.2
N2988279: Q8.2(B) Q8.5(B) R10.2
N2988291: Q10.2(B) Q10.5(B) R14.2
N2988319: Q6.6(C) R5.1
N2988327: Q8.6(C) R9.1
N2988335: Q10.6(C) R13.1

Not connected (* = marked no-connect by the designer): J1 SH1* SH2*; J2 11* 18* 20* 21* 22* 23* 24* 25* 26* 27* 28* 30* 32* 34* 36* 37* 38* 40* 42* 43* 44* 45* 46* 47* 48* 49* 50* 51* 52* 53* 54* 55* 56* 57* 58* 59* 60*; J4 SH1* SH2*; J7 3*; J8 3*; J9 B3* B9 C3* C9 C17; J10 B9* B16* B20* C9* C16* C20*; J11 B9* B17* B18* C9* C17* C18*; J12 B9 B12* B13* C9 C12* C13*; J13 11* 18* 20* 21* 22* 23* 24* 25* 26* 27* 28* 30* 32* 34* 36* 37* 38* 40* 42* 43* 44* 45* 46* 47* 48* 49* 50* 51* 52* 53* 54* 55* 56* 57* 58* 59* 60*

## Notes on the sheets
sheet 1
- Ideal Diode Circuit for 5V Or'ing
- Or'ing Circuit for 15V
sheet 2
- XMC Drive Adapter Card
- CONTENTS
- PAGE
- DESCRIPTION
- 01
- Title, Table of Contents & Drawing Numbers
- 02
- HD Connector
- 03
- Or'ing Circuit
- 04
- M3,M1 & Semtech 1 Connector
- 05
- M5 ,Semtech 2 Connector
- 06
- Expansion Headers
- 07
- Revision History
- Drawing Numbers
- PCBA
- PCB
- FAB DRW
- ASSY DRW
- SCH DRW
sheet 3
- HD Connector
sheet 4
- Semtech Connector 1
- M3,M1 Connector 1
- Selection jumper for Semtech connector 1
- M3,M1 Connector 2
sheet 5
- Semtech Connector 2
- M5 Connector
- Selection jumper for Semtech connector 2
- SPI Drive card interface
sheet 6
- Expansion Header
- Layout Note: J9,J11,J12 & J10 need to 100mil pitch compactible
sheet 7
- REVISION HISTORY
- REV
- DESCRIPTION OF CHANGE
- DATE
- 0.01
- Initial Release
- 2023/02/22
- Added diffrential pair for M3 and M5
  Added provision for 0 OHM for AGND connection
  Rev 01 board released
- 1.00
- 2023/03/13
- Swapped PWM pins as per requirement
  Provided mux option to SPI
  Updated pin as requirement
- 1.01
- 2023/08/22
- HD connector changed to homogenous Symbol
- 2.00
- 2023/09/07
- 3.00
- 3 PAD resistor option is added for M5 connector signal
- 2024/03/13
